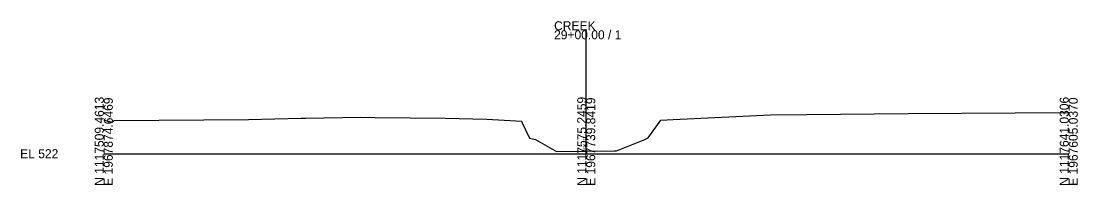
# Model space of a CAD drawing. Extents: x 9974 to 10303, y 9990 to 19550.
# Drawn here: x 9974.3 to 10302.8, y 17990.3 to 18041.2 of the extents above; entities that cross this region are included whole.
import ezdxf

# ---------------------------------------------------------------- set-up
doc = ezdxf.new("R2010")
doc.units = 0
for name, color, linetype in [('Level 10', 7, 'Continuous'), ('Level 60', 7, 'Continuous'), ('Level 63', 7, 'Continuous')]:
    doc.layers.add(name, color=color, linetype=linetype)

msp = doc.modelspace()

# ---------------------------------------------------------------- linework, layer by layer
at = {"layer": 'Level 60'}
for p, q in [((10000, 18010.3), (10000.61, 18010.36)), ((10000.61, 18010.36), (10002.7, 18009.82)), ((10002.7, 18009.82), (10003.27, 18010.32)), ((10003.27, 18010.32), (10045.04, 18010.69)), ((10045.04, 18010.69), (10061.34, 18011.06)), ((10061.34, 18011.06), (10062.83, 18011.1)), ((10062.83, 18011.1), (10079.72, 18011.37)), ((10079.72, 18011.37), (10084.38, 18011.25)), ((10084.38, 18011.25), (10106.13, 18011.01)), ((10106.13, 18011.01), (10119.1, 18010.7)), ((10119.1, 18010.7), (10129.82, 18010.11)), ((10169.29, 18004.89), (10173.23, 18010.39)), ((10173.23, 18010.39), (10177.07, 18010.62)), ((10177.07, 18010.62), (10207.25, 18012.11)), ((10207.25, 18012.11), (10218.49, 18012.21)), ((10218.49, 18012.21), (10250.04, 18012.53)), ((10250.04, 18012.53), (10300, 18012.8)), ((10129.82, 18010.11), (10130.12, 18009.6)), ((10130.12, 18009.6), (10132.31, 18004.85)), ((10132.31, 18004.85), (10134.22, 18004.44)), ((10134.22, 18004.44), (10140.7, 18000.68)), ((10159.45, 18000.87), (10168.25, 18004.44)), ((10168.25, 18004.44), (10169.29, 18004.89)), ((10140.7, 18000.68), (10150, 18000.77)), ((10150, 18000.77), (10158.71, 18000.86)), ((10158.71, 18000.86), (10159.45, 18000.87))]:
    msp.add_line(p, q, dxfattribs=at)
at = {"layer": 'Level 63'}
for p, q in [((10150, 18000), (10150, 18038.39)), ((10000, 18000), (10150, 18000)), ((10150, 18000), (10300, 18000))]:
    msp.add_line(p, q, dxfattribs=at)

# ---------------------------------------------------------------- texts
at = {"layer": 'Level 10'}
msp.add_text('522.772', height=0.8, rotation=90, dxfattribs=at).set_placement((10149.9, 18001.27))
at = {"layer": 'Level 63'}
for s, p in [('CREEK', (10140, 18038.39)), ('29+00.00 / 1', (10140, 18035.59)), ('EL 522', (9974, 17998.6))]:
    msp.add_text(s, height=2.8, dxfattribs=at).set_placement(p)
for s, p in [('N 1117509.4613', (10000, 17990)), ('E 1967874.6469', (10002.8, 17990)), ('N 1117575.2459', (10150, 17990)), ('E 1967739.8419', (10152.8, 17990)), ('N 1117641.0306', (10300, 17990)), ('E 1967605.0370', (10302.8, 17990))]:
    msp.add_text(s, height=2.8, rotation=90, dxfattribs=at).set_placement(p)

doc.saveas('drawing.dxf')
